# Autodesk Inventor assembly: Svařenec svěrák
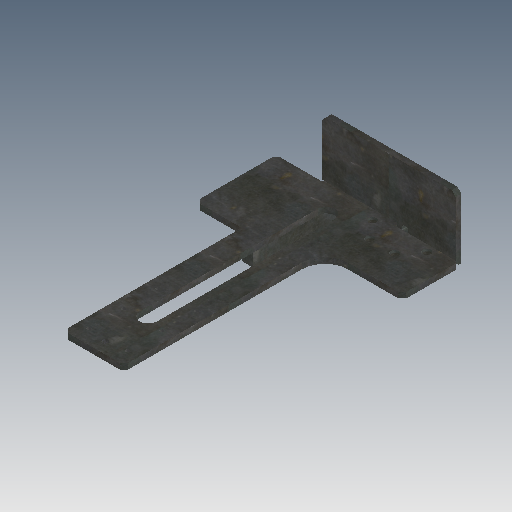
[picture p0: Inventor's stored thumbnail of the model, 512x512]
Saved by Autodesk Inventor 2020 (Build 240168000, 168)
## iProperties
Created: 2025-03
Part Number: Svařenec svěrák
Document SubType Name: Assembly
Designer: doma
Mass: 8374.51 g
Surface Area: 2466.58 cm^2
Volume: 1066.82 cm^3
Density: 7.85 g/cm^3
Author: doma
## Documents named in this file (6)
- C:\Users\doma\Desktop\Pásovka záloha\Workgroups\NotInProject\Svařenec svěrák tělo.iam
- C:\Users\doma\Desktop\Pásovka záloha\Workgroups\NotInProject\Svěrák pevná čelist.ipt
- C:\Users\doma\Desktop\Pásovka záloha\Workgroups\NotInProject\Svěrák tělo.ipt
- C:\Users\doma\Desktop\Pásovka záloha\Workgroups\NotInProject\Podložka v10.ipt
- C:\Users\doma\Desktop\Pásovka záloha\Workgroups\NotInProject\Výztuha pevné čelisti 1.ipt
- C:\Users\doma\Desktop\Pásovka záloha\Workgroups\NotInProject\Výztuha pevné čelisti 2.ipt
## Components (8 placed, 5 different names)
1. Svěrák pevná čelist:1 — Proti sobě:1, Proti sobě:2, Stejný směr:2, Proti sobě:15, Proti sobě:16
2. Svěrák tělo:1 — Proti sobě:1, Proti sobě:2, Proti sobě:3, Proti sobě:4, Proti sobě:5, Proti sobě:6, Proti sobě:7, Stejný směr:3, Proti sobě:11, Proti sobě:12, Proti sobě:13, Proti sobě:14, Proti sobě:15
3. Podložka v10:1 — Proti sobě:3, Proti sobě:14
4. Podložka v10:2 — Proti sobě:4, Proti sobě:12
5. Podložka v10:3 — Proti sobě:5, Proti sobě:13
6. Podložka v10:4 — Proti sobě:6, Proti sobě:11
7. Výztuha pevné čelisti 1:1 — Proti sobě:7, Stejný směr:2, Stejný směr:3, Proti sobě:9, Proti sobě:10, Úhel:1
8. Výztuha pevné čelisti 2:1 — Proti sobě:9, Proti sobě:10, Úhel:1, Proti sobě:16
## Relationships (18: Mate 15, Flush 2, Angle 1)
- Proti sobě:1 [Mate]: Svěrák pevná čelist:1 ↔ Svěrák tělo:1
- Proti sobě:2 [Mate]: Svěrák pevná čelist:1 ↔ Svěrák tělo:1
- Proti sobě:3 [Mate]: Svěrák tělo:1 ↔ Podložka v10:1
- Proti sobě:4 [Mate]: Svěrák tělo:1 ↔ Podložka v10:2
- Proti sobě:5 [Mate]: Svěrák tělo:1 ↔ Podložka v10:3
- Proti sobě:6 [Mate]: Svěrák tělo:1 ↔ Podložka v10:4
- Proti sobě:7 [Mate]: Svěrák tělo:1 ↔ Výztuha pevné čelisti 1:1
- Stejný směr:2 [Flush]: Svěrák pevná čelist:1 ↔ Výztuha pevné čelisti 1:1
- Stejný směr:3 [Flush]: Svěrák tělo:1 ↔ Výztuha pevné čelisti 1:1
- Proti sobě:9 [Mate]: Výztuha pevné čelisti 1:1 ↔ Výztuha pevné čelisti 2:1
- Proti sobě:10 [Mate]: Výztuha pevné čelisti 1:1 ↔ Výztuha pevné čelisti 2:1
- Úhel:1 [Angle]: Výztuha pevné čelisti 1:1 ↔ Výztuha pevné čelisti 2:1
- Proti sobě:11 [Mate]: Svěrák tělo:1 ↔ Podložka v10:4
- Proti sobě:12 [Mate]: Svěrák tělo:1 ↔ Podložka v10:2
- Proti sobě:13 [Mate]: Svěrák tělo:1 ↔ Podložka v10:3
- Proti sobě:14 [Mate]: Svěrák tělo:1 ↔ Podložka v10:1
- Proti sobě:15 [Mate]: Svěrák pevná čelist:1 ↔ Svěrák tělo:1
- Proti sobě:16 [Mate]: Svěrák pevná čelist:1 ↔ Výztuha pevné čelisti 2:1
